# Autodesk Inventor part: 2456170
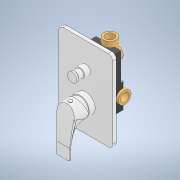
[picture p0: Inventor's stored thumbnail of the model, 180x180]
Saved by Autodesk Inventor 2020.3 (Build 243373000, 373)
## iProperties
Created: 2021-08
Part Number: 2456170
Material: Ogólny
Description: SIGMA Bateria wannowo-natryskowa podtynkowa
Document SubType Name: Modeling
Designer: Gabriela W.
Density: 1 g/cm^3
Appearance: Domyślna
Title: C:\Nextcloud\02_biblioteki_cad\Valvex\Projekt\PROJECTS\Eksport\ETAP 4\2456170\2456170.stp
Author: Cadventure
Sending System: Autodesk Inventor 2020
Preprocessor: ST-DEVELOPER v18.1
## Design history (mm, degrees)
feature "Bryła2"
feature "Bryła3"
feature "Bryła4:1"
node "Bryła1"
node "Bryła4"
node "Bryła5"
